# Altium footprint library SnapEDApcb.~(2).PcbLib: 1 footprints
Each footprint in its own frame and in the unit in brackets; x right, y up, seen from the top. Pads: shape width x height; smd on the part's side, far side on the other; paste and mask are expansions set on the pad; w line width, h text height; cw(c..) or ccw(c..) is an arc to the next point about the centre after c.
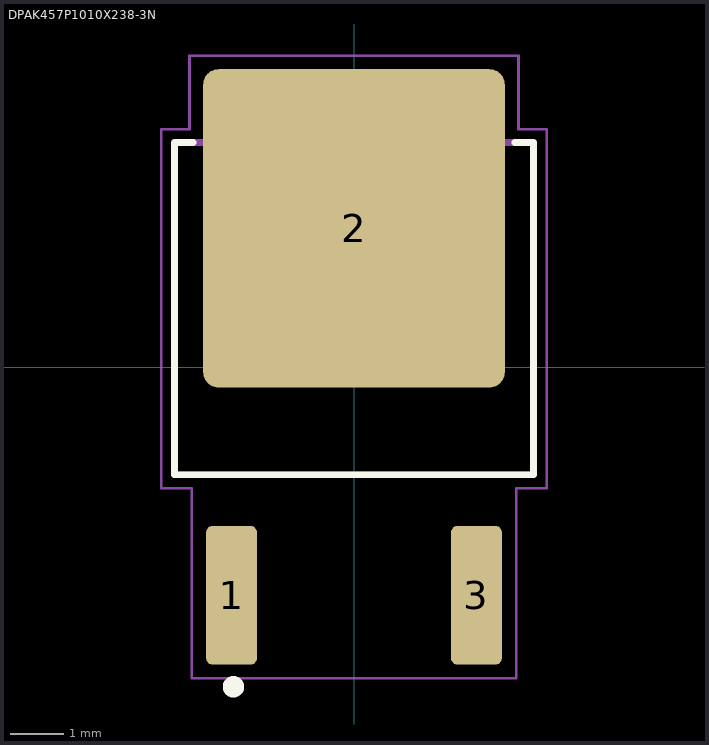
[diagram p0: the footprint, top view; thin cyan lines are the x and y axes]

## DPAK457P1010X238-3N [mm]
pads (3):
  rrect25% 0.95x2.59 smd: 1(-2.286,-4.26) 3(2.286,-4.26)
  rrect10% 5.63x5.94 smd: 2(0,2.59)
Top Overlay:
  circle w0.2: c-2.25,-5.969 r0.1
  lines w0.127: -3,4.19 -3.35,4.19 -3.35,-2.01 3.35,-2.01 3.35,4.19 3,4.19
Mechanical 13:
  lines w0.127: -3.35,-2.01 -3.35,4.19 3.35,4.19 3.35,-2.01 -3.35,-2.01
Mechanical 15:
  lines w0.05: -3.6,-2.26 -3.03,-2.26 -3.03,-5.81 3.03,-5.81 3.03,-2.26 3.6,-2.26 3.6,4.44 3.07,4.44 3.07,5.81 -3.07,5.81 -3.07,4.44 -3.6,4.44 -3.6,-2.26
3D body: height 0.25, standoff 0, extent 0,0 0,0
